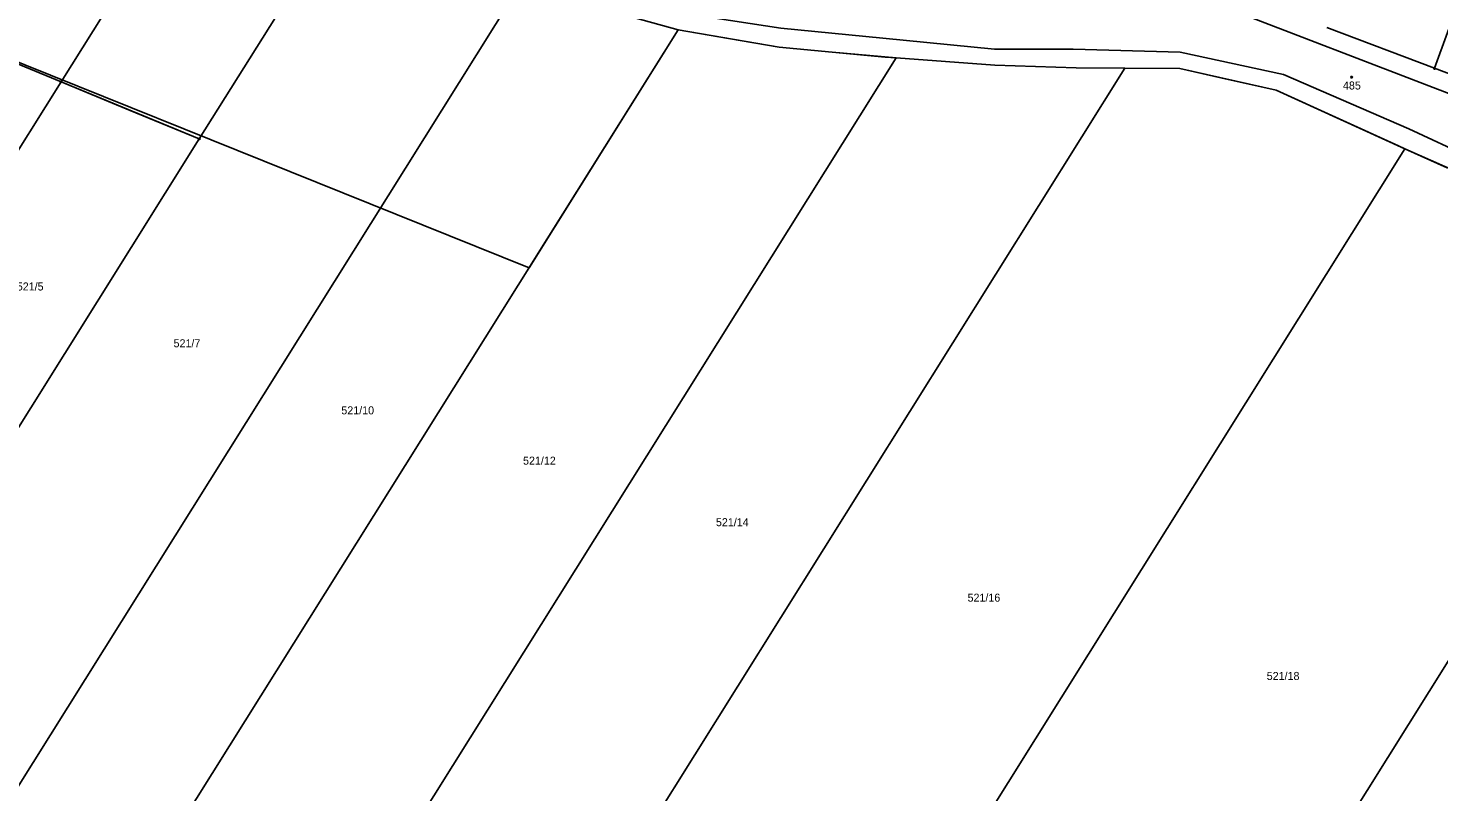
# Model space of a CAD drawing. Extents: x -634640 to -629202, y -1196156 to -1190068.
# Drawn here: x -631489.7 to -631190.1, y -1193075.2 to -1192913 of the extents above; entities that cross this region are included whole.
import ezdxf

# ---------------------------------------------------------------- set-up
doc = ezdxf.new("R2010")
doc.units = 0
for name, color, linetype in [('Obvod šetřený', 7, 'Continuous'), ('Vrstva 1', 7, 'Continuous'), ('Vrstva 2', 7, 'Continuous'), ('Vrstva 3', 7, 'Continuous'), ('Vrstva 8', 7, 'Continuous')]:
    doc.layers.add(name, color=color, linetype=linetype)

msp = doc.modelspace()

# ---------------------------------------------------------------- linework, layer by layer
at = {"layer": 'Obvod šetřený'}
for points in [[(-631453.34, -1192936.49), (-631468.02, -1192930.43), (-631482.7, -1192924.37), (-631510.81, -1192912.78), (-631526.055, -1192906.495), (-631541.3, -1192900.21), (-631547.7, -1192910.19), (-631575.23, -1192947.14), (-631602.76, -1192984.09)], [(-631541.3, -1192900.21), (-631383.293, -1192963.849), (-631351.65, -1192913.33)], [(-631188.27, -1192942.6), (-631197.26, -1192938.59), (-631224.61, -1192926.14), (-631234.84, -1192923.835), (-631245.07, -1192921.53), (-631256.77, -1192921.47), (-631267.08, -1192921.41), (-631275.73, -1192921.105), (-631284.38, -1192920.8), (-631294.855, -1192920.035), (-631305.33, -1192919.27), (-631318.905, -1192918.06), (-631330.16, -1192917.02), (-631340.905, -1192915.175), (-631351.65, -1192913.33), (-631382.44, -1192962.49)]]:
    msp.add_lwpolyline(points, dxfattribs=at)
at = {"layer": 'Vrstva 1'}
for p, q in [((-631454.36, -1192879.11), (-631482.7, -1192924.37)), ((-631178.32, -1192886.73), (-631190.98, -1192921.49)), ((-631424.63, -1192890.64), (-631453.34, -1192936.49)), ((-631385.28, -1192903.9), (-631512.56, -1193107.16)), ((-631184.25, -1192928.26), (-631243.17, -1192905.59)), ((-631351.65, -1192913.33), (-631367.29, -1192909)), ((-631329.8, -1192912.98), (-631346.99, -1192910.33)), ((-631351.65, -1192913.33), (-631475.58, -1193111.19)), ((-631330.16, -1192917.02), (-631351.65, -1192913.33)), ((-631308.16, -1192915.1), (-631329.8, -1192912.98)), ((-631190.98, -1192921.49), (-631213.87, -1192912.8)), ((-631307.65, -1192919.1), (-631330.16, -1192917.02)), ((-631284.41, -1192917.41), (-631308.16, -1192915.1)), ((-631267.76, -1192917.41), (-631284.41, -1192917.41)), ((-631244.98, -1192918.05), (-631267.76, -1192917.41)), ((-631305.33, -1192919.27), (-631428.71, -1193116.3)), ((-631305.33, -1192919.27), (-631307.65, -1192919.1)), ((-631284.38, -1192920.8), (-631305.33, -1192919.27)), ((-631223.04, -1192922.81), (-631244.98, -1192918.05)), ((-631256.77, -1192921.47), (-631381.96, -1193121.39)), ((-631267.08, -1192921.41), (-631284.38, -1192920.8)), ((-631256.77, -1192921.47), (-631267.08, -1192921.41)), ((-631245.07, -1192921.53), (-631256.77, -1192921.47)), ((-631224.61, -1192926.14), (-631245.07, -1192921.53)), ((-631196.44, -1192934.33), (-631223.04, -1192922.81)), ((-631183.02, -1192924.51), (-631190.98, -1192921.49)), ((-631482.7, -1192924.37), (-631591.76, -1193098.54)), ((-631482.7, -1192924.37), (-631453.34, -1192936.49)), ((-631198.61, -1192937.99), (-631224.61, -1192926.14)), ((-631176.63, -1192943.59), (-631196.44, -1192934.33)), ((-631453.34, -1192936.49), (-631557.17, -1193102.3)), ((-631197.26, -1192938.59), (-631198.61, -1192937.99)), ((-631197.26, -1192938.59), (-631316.22, -1193128.55)), ((-631179.28, -1192946.61), (-631197.26, -1192938.59)), ((-631139.85, -1192970.36), (-631243.84, -1193136.43))]:
    msp.add_line(p, q, dxfattribs=at)
at = {"layer": 'Vrstva 3'}
msp.add_lwpolyline([(-631208.51, -1192923.22), (-631208.42, -1192923.37), (-631208.51, -1192923.52), (-631208.69, -1192923.52), (-631208.78, -1192923.37), (-631208.69, -1192923.22), (-631208.51, -1192923.22)], dxfattribs=at)
at = {"layer": 'Vrstva 8'}
for points in [[(-631190.89, -1192921.34), (-631190.8, -1192921.49), (-631190.89, -1192921.64), (-631191.07, -1192921.64), (-631191.16, -1192921.49), (-631191.07, -1192921.34), (-631190.89, -1192921.34)], [(-631482.61, -1192924.22), (-631482.52, -1192924.37), (-631482.61, -1192924.52), (-631482.79, -1192924.52), (-631482.88, -1192924.37), (-631482.79, -1192924.22), (-631482.61, -1192924.22)], [(-631453.25, -1192936.34), (-631453.16, -1192936.49), (-631453.25, -1192936.64), (-631453.43, -1192936.64), (-631453.52, -1192936.49), (-631453.43, -1192936.34), (-631453.25, -1192936.34)]]:
    msp.add_lwpolyline(points, dxfattribs=at)

# ---------------------------------------------------------------- texts
at = {"layer": 'Vrstva 2'}
for s, p in [('485', (-631210.433, -1192925.99)), ('521/5', (-631492.093, -1192968.69)), ('521/7', (-631458.793, -1192980.76)), ('521/10', (-631423.163, -1192995.01)), ('521/12', (-631384.573, -1193005.7)), ('521/14', (-631343.603, -1193018.77)), ('521/16', (-631290.163, -1193034.81)), ('521/18', (-631226.623, -1193051.44))]:
    msp.add_text(s, height=1.7, dxfattribs=at).set_placement(p)

doc.saveas('drawing.dxf')
